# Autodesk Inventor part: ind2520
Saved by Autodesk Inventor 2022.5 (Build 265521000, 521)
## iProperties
Created: 2024-12
Part Number: ind2520
Material: Generic
Document SubType Name: Modeling
Designer: AdminForWorker
Density: 1 g/cm^3
Appearance: Default
Title: ind2520 v1
Author: AdminForWorker
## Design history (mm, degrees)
feature "Body4"
feature "Body5"
feature "Body6"
body "Solid1"
body "Solid2"
body "Solid3"
